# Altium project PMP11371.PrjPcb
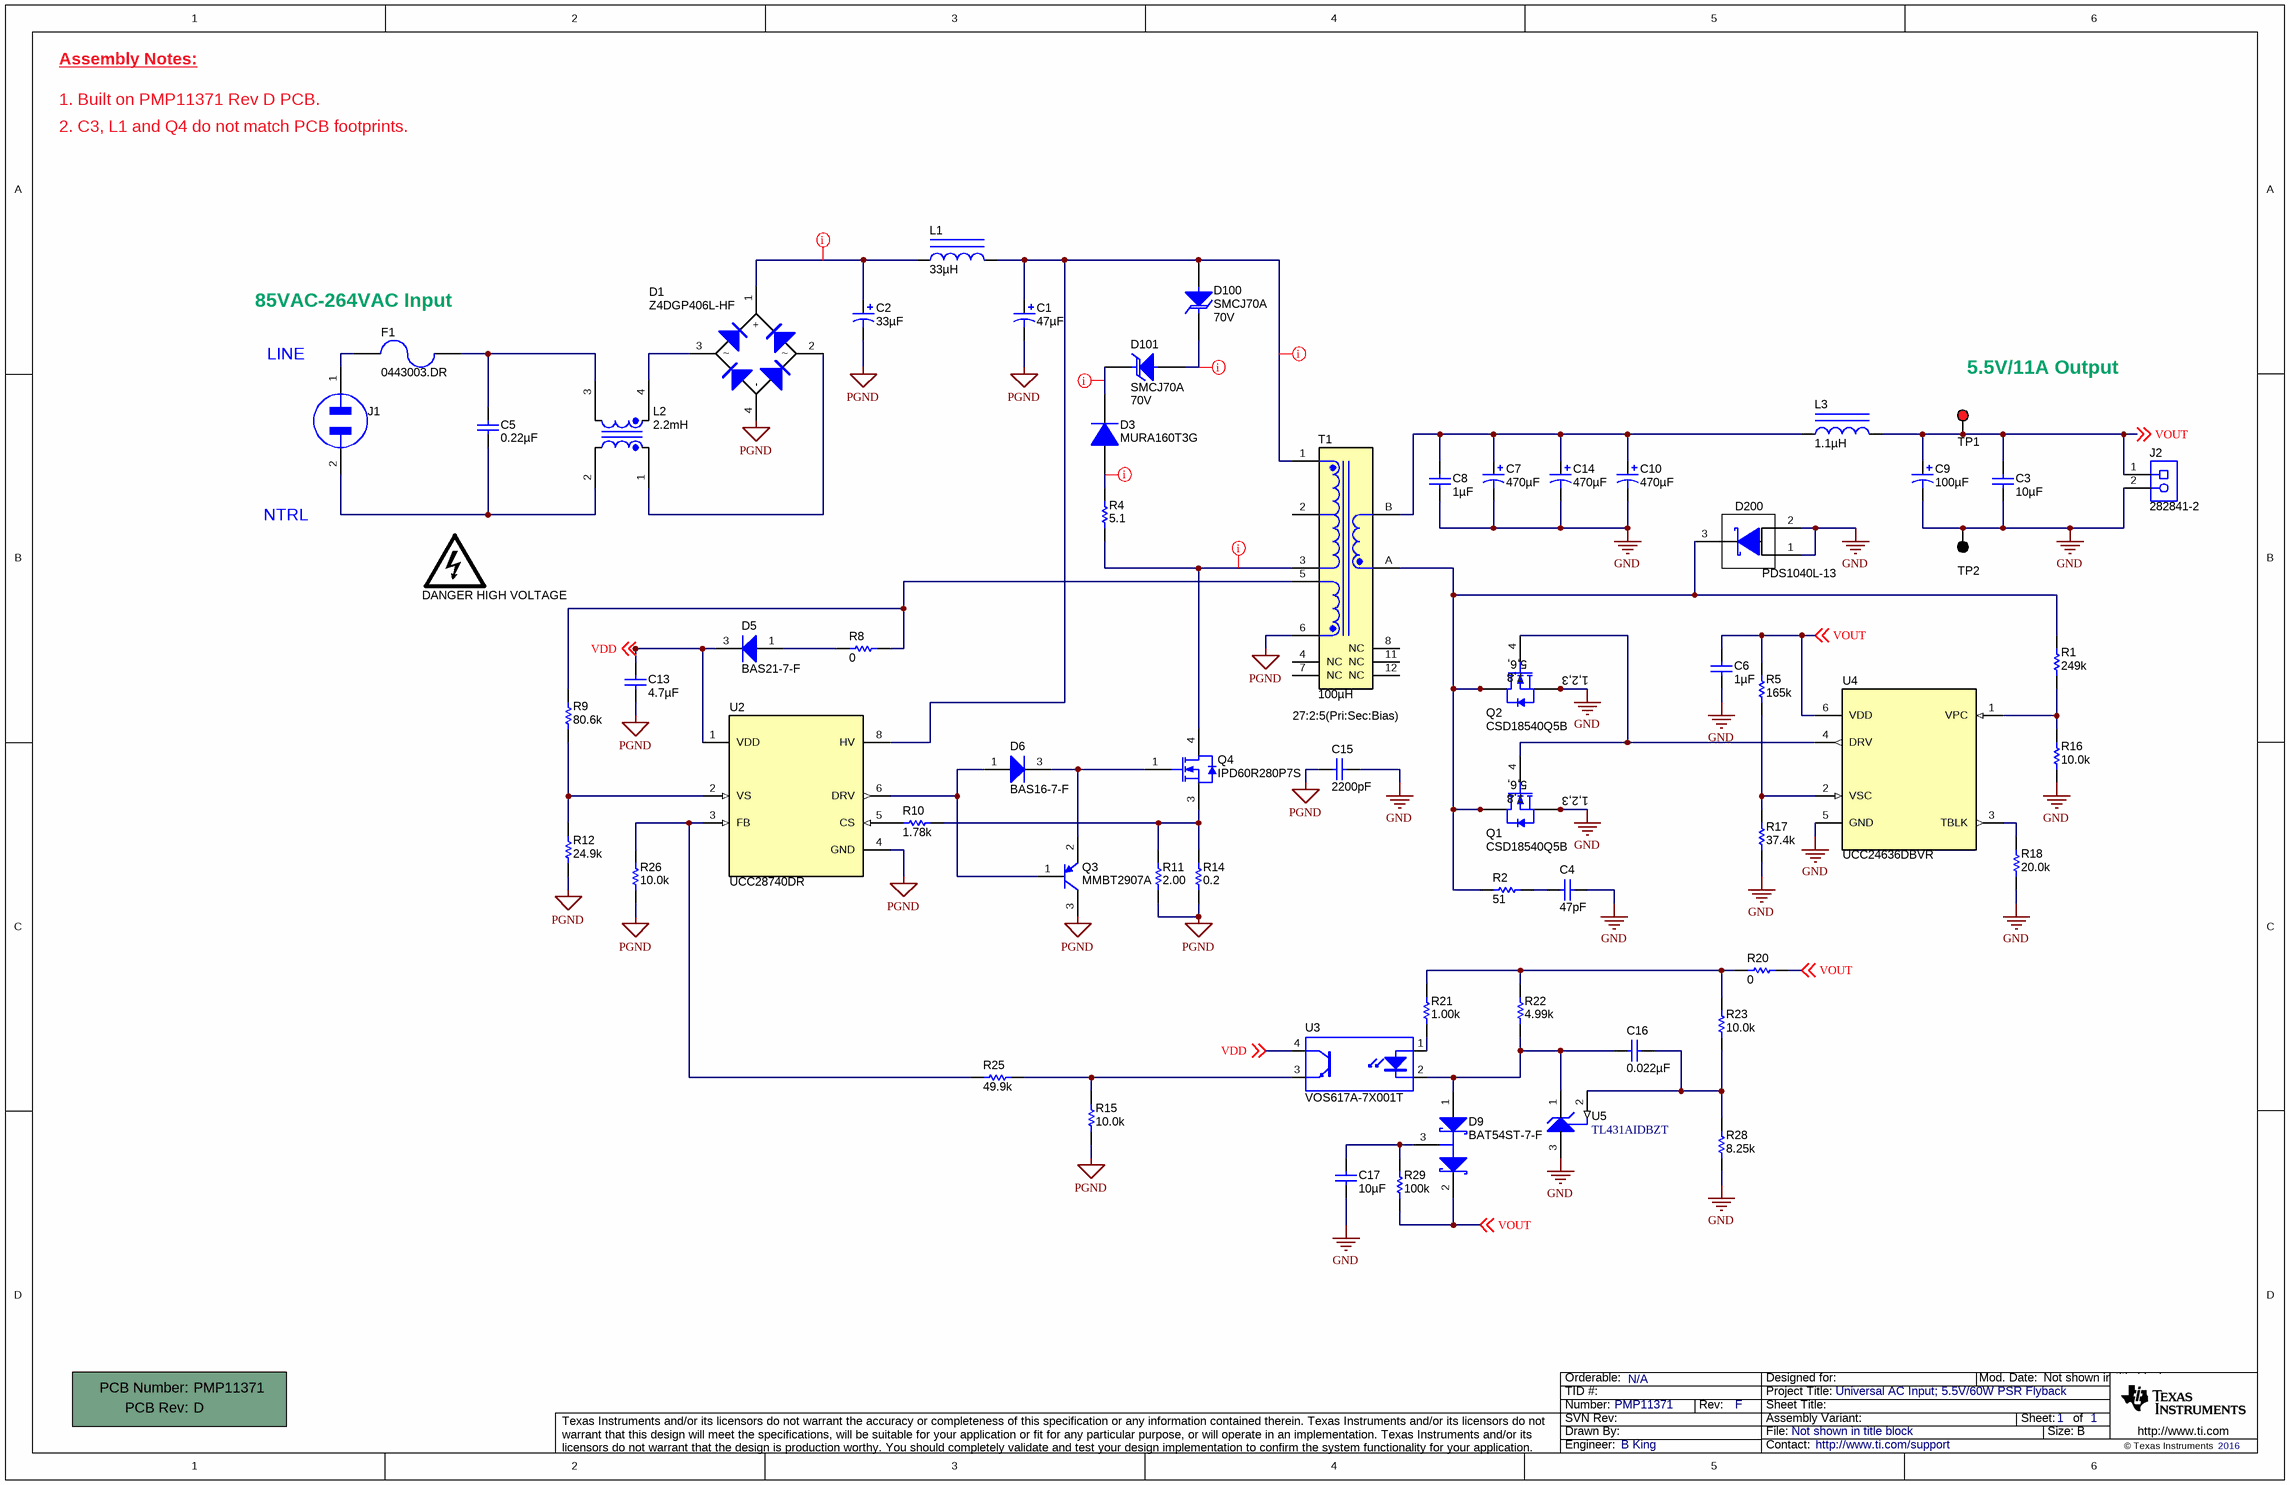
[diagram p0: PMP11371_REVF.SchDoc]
TechSupport: http://www.ti.com/support; SCH_Rev: F; PRJ_Title: Universal AC Input; 5.5V/60W PSR Flyback; PRJ_Number: PMP11371; PRJ_Engineer: B King; PCB_Rev: D; PCB_Layout: B King; EVM_Orderable: N/A; CopyrightYear: 2016
1 sheet, 64 parts. Net scope: global (net labels, ports and power ports of the same name join across sheets).
Board file: PMP11371_REVD.PcbDoc

## Sheet PMP11371_REVF.SchDoc
size 431 x 279 mm; Date: Not shown in title block; ApprovedBy: Not shown in title block; CheckedBy: Not shown in title block; Author: Not shown in title block; CompanyName: Not shown in title block; Engineer: Not shown in title block; Organization: Not shown in title block; Address1: Not shown in title block; Address2: Not shown in title block; Address3: Not shown in title block; Address4: Not shown in title block; DocumentNumber: 1; Revision: Use project parameter SCH_Rev; SheetNumber: 1; SheetTotal: 1; PageSetup: Record=PageOptions¦CenterHorizontal=True¦CenterVertical=True¦PrintScale=1.00¦XCorrection=1.00¦YCorrection=1.00¦PrintKind=0¦BorderSize=5000000¦LeftOffset=0¦BottomOffset=0¦Orientation=2¦PaperLength=1000¦PaperWidth=1000¦Scale=100¦PaperSource=15¦PrintQuality=600¦MediaType=1¦DitherType=10¦PaperKind=Letter¦PrintScaleMode=1

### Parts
!PCB  Printed Circuit Board  (value not drawn)  (mechanical)
C1  ValueDisplayed: 47µF  [CAPPR7.5-16X25]  (hidden comment: EEUED2G470)
C2  ValueDisplayed: 33µF  [CAPPR7.5-16X20]  (hidden comment: EEUED2G330S)
C3  ValueDisplayed: 10µF  [0805L]  (hidden comment: GRM21BR61C106KE15L)
C4  ValueDisplayed: 47pF  [0402L]  (hidden comment: GRM1555C1H470FA01D)
C5  ValueDisplayed: 0.22µF  [WCAP-FTX2_1800x600x1150]  (hidden comment: 890324025027CS)
C6  ValueDisplayed: 1µF  [0402L]  (hidden comment: GRM155R61A105KE15D)
C7  ValueDisplayed: 470µF  [CAPPRD350W60D800H800]  (hidden comment: 16SEPC470M)
C8  ValueDisplayed: 1µF  [0402L]  (hidden comment: GRM155R61A105KE15D)
C9  ValueDisplayed: 100µF  [CAPPR250W50D630H1120]  (hidden comment: EEU-EB1E101S)
C10  ValueDisplayed: 470µF  [CAPPRD350W60D800H800]  (hidden comment: 16SEPC470M)
C13  ValueDisplayed: 4.7µF  [1206_180L]  (hidden comment: GRM31CR71H475KA12L)
C14  ValueDisplayed: 470µF  [CAPPRD350W60D800H800]  (hidden comment: 16SEPC470M)
C15  ValueDisplayed: 2200pF  [CAPRD750W60D1050H1450]  (hidden comment: CS11-E2GA222MYNS)
C16  ValueDisplayed: 0.022µF  [0402L]  (hidden comment: GRM155R71H223KA12D)
C17  ValueDisplayed: 10µF  [0805L]  (hidden comment: GRM219R61A106KE44D)
D1  Z4DGP406L-HF  [Z4-D]
D3  MURA160T3G  [SMA]
D5  BAS21-7-F  [SOT-23]
D6  BAS16-7-F  [SOT-23]
D9  BAT54ST-7-F  [SOT-523]
D100  SMCJ70A  value 70V  [SMC_265]
D101  SMCJ70A  value 70V  [SMC_265]
D200  PDS1040L-13  [PowerDI5]
F1  0443003.DR  [FUSE_0443]
J1  770W-X2/10  [CONN_AC_770W-SERIES]  (value not drawn)
J2  282841-2  [TEC_282841-2]
L1  ValueDisplayed: 33µH  [DR73]  (hidden comment: DR73-330-R)
L2  ValueDisplayed: 2.2mH  [IND_WE-CMB-S]  (hidden comment: 744822222)
L3  ValueDisplayed: 1.1µH  [WE-HCI_7050]  (hidden comment: 744314110)
LOGO1  DANGER HIGH VOLTAGE  [IEC_HighVoltage_Small]  (no BOM)
Q1  CSD18540Q5B  [TRANS_NexFET_Q5B]
Q2  CSD18540Q5B  [TRANS_NexFET_Q5B]
Q3  MMBT2907A  [SOT-23]
Q4  IPD60R280P7S  [DDPAK]
R1  ValueDisplayed: 249k  [0402L]  (hidden comment: CRCW0402249KFKED)
R2  ValueDisplayed: 51  [1206L]  (hidden comment: CRCW120651R0JNEA)
R4  ValueDisplayed: 5.1  [2010L]  (hidden comment: CRCW20105R10JNEF)
R5  ValueDisplayed: 165k  [0402L]  (hidden comment: CRCW0402165KFKED)
R8  ValueDisplayed: 0  [0402L]  (hidden comment: CRCW04020000Z0ED)
R9  ValueDisplayed: 80.6k  [0402L]  (hidden comment: CRCW040280K6FKED)
R10  ValueDisplayed: 1.78k  [0402L]  (hidden comment: CRCW04021K78FKED)
R11  ValueDisplayed: 2.00  [0603L]  (hidden comment: CRCW06032R00FKEA)
R12  ValueDisplayed: 24.9k  [0402L]  (hidden comment: CRCW040224K9FKED)
R14  ValueDisplayed: 0.2  [2010L]  (hidden comment: CSRN2010FKR200)
R15  ValueDisplayed: 10.0k  [0402L]  (hidden comment: CRCW040210K0FKED)
R16  ValueDisplayed: 10.0k  [0402L]  (hidden comment: CRCW040210K0FKED)
R17  ValueDisplayed: 37.4k  [0402L]  (hidden comment: CRCW040237K4FKED)
R18  ValueDisplayed: 20.0k  [0402L]  (hidden comment: CRCW040220K0FKED)
R20  ValueDisplayed: 0  [0402L]  (hidden comment: CRCW04020000Z0ED)
R21  ValueDisplayed: 1.00k  [0402L]  (hidden comment: CRCW04021K00FKED)
R22  ValueDisplayed: 4.99k  [0402L]  (hidden comment: CRCW04024K99FKED)
R23  ValueDisplayed: 10.0k  [0402L]  (hidden comment: CRCW040210K0FKED)
R25  ValueDisplayed: 49.9k  [0402L]  (hidden comment: CRCW040249K9FKED)
R26  ValueDisplayed: 10.0k  [0402L]  (hidden comment: CRCW040210K0FKED)
R28  ValueDisplayed: 8.25k  [0402L]  (hidden comment: CRCW04028K25FKED)
R29  ValueDisplayed: 100k  [0402L]  (hidden comment: CRCW0402100KFKED)
T1  ValueDisplayed: 100µH  [Renco_RLTI-1174]  (hidden comment: RLTI-1174)
TP1  5000  [Keystone5000]  (value not drawn)
TP2  5001  [Keystone5001]  (value not drawn)
U2  UCC28740DR  [D0007A_L]
U3  VOS617A-7X001T  [SSOP-4_VISHAY]
U4  UCC24636DBVR  [DBV0006A_N]
U5  TL431AIDBZT  [DBZ0003A_L]

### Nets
GND: C3.2 C4.1 C6.2 C7.2(-) C8.2 C9.2(-) C10.2(-) C14.2(-) C15.1 C17.2 D200.1(A) D200.2(A) J2.2 Q1.1(S) Q1.2(S) Q1.3(S) Q2.1(S) Q2.2(S) Q2.3(S) R16.1 R17.1 R18.1 R28.1 TP2.1 U4.5(GND) U5.3(ANODE)
PGND: C1.2(-) C2.2(-) C13.2 C15.2 D1.4(-) Q3.3(C) R11.1 R12.1 R14.1 R15.1 R26.1 T1.6 U2.4(GND)
VDD: C13.1 D5.3(K) U2.1(VDD) U3.4(C) ; off-sheet VDD
VOUT: C3.1 C6.1 C9.1(+) D9.2(K) J2.1 L3.2 R5.2 R20.1 R29.1 TP1.1 U4.6(VDD) ; off-sheet VOUT
NetC1_1: C1.1(+) D100.2(A) L1.2 T1.1 U2.8(HV)
NetC2_1: C2.1(+) D1.1(+) L1.1
NetC4_2: C4.2 R2.1
NetC5_1: C5.1 F1.1 L2.3
NetC5_2: C5.2 J1.2(Hot) L2.2
NetC7_1: C7.1(+) C8.1 C10.1(+) C14.1(+) L3.1 T1.B(SR)
NetC16_1: C16.1 D9.1(A) R22.1 U3.2(K) U5.1(CATHODE)
NetC16_2: C16.2 R23.1 R28.2 U5.2(REF)
NetC17_1: C17.1 D9.3(C) R29.2
NetD1_2: D1.2 L2.1
NetD1_3: D1.3 L2.4
NetD3_1: D3.1(K) D101.1(K)
NetD3_2: D3.2(A) R4.2
NetD5_1: D5.1(A) R8.2
NetD6_1: D6.1(A) Q3.1(B) U2.6(DRV)
NetD6_3: D6.3(K) Q3.2(E) Q4.1(G)
NetD100_1: D100.1(K) D101.2(A)
NetD200_3: D200.3(K) Q1.5(D) Q1.6(D) Q1.7(D) Q1.8(D) Q2.5(D) Q2.6(D) Q2.7(D) Q2.8(D) R1.2 R2.2 T1.A(5.5V)
NetF1_2: F1.2 J1.1(Neutral)
NetQ1_4: Q1.4(G) Q2.4(G) U4.4(DRV)
NetQ4_3: Q4.3(S) R10.2 R11.2 R14.2
NetQ4_4: Q4.4(D) R4.1 T1.3
NetR1_1: R1.1 R16.2 U4.1(VPC)
NetR5_1: R5.1 R17.2 U4.2(VSC)
NetR8_1: R8.1 R9.2 T1.5
NetR9_1: R9.1 R12.2 U2.2(VS)
NetR10_1: R10.1 U2.5(CS)
NetR15_2: R15.2 R25.1 U3.3(E)
NetR18_2: R18.2 U4.3(TBLK)
NetR20_2: R20.2 R21.1 R22.2 R23.2
NetR21_2: R21.2 U3.1(A)
NetR25_2: R25.2 R26.2 U2.3(FB)

Not connected (* = marked no-connect by the designer): T1 2 4(NC) 7(NC) 8(NC) 11(NC) 12(NC)

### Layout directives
rule Clearance Constraint [Clearance = 15mil]: NetC1_1, NetD3_1, NetD3_2, NetD100_1, NetQ4_4
rule Clearance Constraint [Clearance = 20mil]: NetC2_1

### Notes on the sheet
- Assembly Notes:
- 1. Built on PMP11371 Rev D PCB.
- 2. C3, L1 and Q4 do not match PCB footprints.
- (near F1) 85VAC-264VAC Input
- (near J1) LINE
- (near TP1) 5.5V/11A Output
- NTRL
- 27:2:5(Pri:Sec:Bias)

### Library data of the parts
!PCB = PCB: Manufacturer: Any; PartNumber: PMP11371; SymbolCreator: a0412235
C1 = EEUED2G470: CAP, AL, 47 µF, 400 V, +/- 20%, 0.609529 ohm, TH; Manufacturer: Panasonic; Polarized: Y; CompType: Capacitor; Value: 47uF; U/M: EA; Cap_F: 0.000047; Tolerance_%: 20; VDC_V: 400; Value2: 400V; IRMS_A: 0.84; TaMin_C: -25; TaMax_C: 105; AC_Derating: 0.3; AEC Category: Q200
C2 = EEUED2G330S: CAP, AL, 33 µF, 400 V, +/- 20%, 0.868117 ohm, TH; Manufacturer: Panasonic; Polarized: Y; CompType: Capacitor; Value: 33uF; U/M: EA; Cap_F: 0.000033; Tolerance_%: 20; VDC_V: 400; Value2: 400V; IRMS_A: 0.73; TaMin_C: -25; TaMax_C: 105; AC_Derating: 0.3; AEC Category: Q200
C3 = GRM21BR61C106KE15L: CAP, CERM, 10 µF, 16 V, +/- 10%, X5R, 0805; Manufacturer: MuRata; Polarized: N; CompType: Capacitor; Value: 10uF; U/M: EA; Cap_F: 0.00001; Tolerance_%: 10; ESR_ohm: 0.008; Value1: 0.008 ohm; VDC_V: 16; Value2: 16V; TaMin_C: -55; TaMax_C: 85; Cap_Case: 0805; SizeArea_mm2: 2.5; SizeAreaWB_mm2: 6.75; SizeX_mm: 2; SizeY_mm: 1.25; SizeZ_mm: 1.45; AEC Category: Q200
C4 = GRM1555C1H470FA01D: CAP, CERM, 47 pF, 50 V, +/- 1%, C0G/NP0, 0402; Manufacturer: MuRata; Polarized: N; CompType: Capacitor; Value: 47pF; U/M: EA; Cap_F: 0.000000000047; Tolerance_%: 1; Value1: Unknown; VDC_V: 50; Value2: 50V; TaMin_C: -55; TaMax_C: 125; Cap_Case: 0402
C5 = 890324025027CS: CAP, Film, 0.22 µF, 275 V, +/- 10%, TH; Manufacturer: Wurth Elektronik; Polarized: N; CompType: Capacitor; Value: 0.22uF; U/M: EA; Cap_F: 0.00000022; Tolerance_%: 10; Value1: Unknown; VDC_V: 275; Value2: 275V; TaMin_C: -40; TaMax_C: 105; Cap_Case: 18x11.5x6mm; AEC Category: Q200
C6 C8 = GRM155R61A105KE15D: CAP, CERM, 1uF, 10V, +/-10%, X5R, 0402; Manufacturer: MuRata; Polarized: N; CompType: Capacitor; U/M: EA; Cap_F: 0.000001; Tolerance_%: 10; Value1: Unknown; TaMin_C: -55; TaMax_C: 85; Cap_Case: 0402
C7 C10 C14 = RL80J821MDN1KX: CAP POLYMER 470UF 20% 16V T/H; Manufacturer: Panasonic; Polarized: Y; CompType: Capacitor; U/M: EA; Cap_F: 0.00082; Tolerance_%: 20; Value1: 0.008 ohm; VDC_V: 6.3; ESR_ohm: 0.008; IRMS_A: 5.7; TaMin_C: -55; TaMax_C: 105; Cap_Case: Radial 3.5-8 x 8
C9 = EEU-EB1E101S: CAP, AL, 100 µF, 25 V, +/- 20%, TH; Manufacturer: Panasonic; Polarized: Y; CompType: Capacitor; Value: 100uF; U/M: EA; Cap_F: 0.0001; Tolerance_%: 20; Value1: Unknown; VDC_V: 25; Value2: 25V; IRMS_A: 0.095; TaMin_C: -40; TaMax_C: 105; Cap_Case: Radial 6.3x11.2; AEC Category: Q200; AEC Qualified: N
C13 = GRM31CR71H475KA12L: CAP, CERM, 4.7 µF, 50 V, +/- 10%, X7R, 1206; Manufacturer: MuRata; Polarized: N; CompType: Capacitor; Value: 4.7uF; U/M: EA; Cap_F: 0.0000047; Tolerance_%: 10; Value1: Unknown; VDC_V: 50; Value2: 50V; TaMin_C: -55; TaMax_C: 125; Cap_Case: 2220; AEC Category: Q200
C15 = CS11-E2GA222MYNS: CAP, CERM, 2200 pF, 250 V, +/- 20%, E, Radial Disc D10.5x7mm; Manufacturer: TDK; Polarized: N; CompType: Capacitor; Value: 2200pF; U/M: EA; Cap_F: 0.0000000022; Tolerance_%: 20; Value1: Unknown; VDC_V: 250; Value2: 250V; TaMin_C: -25; TaMax_C: 105; Cap_Case: Disc, 10.5x7mm
C16 = GRM155R71H223KA12D: CAP, CERM, 0.022 µF, 50 V, +/- 10%, X7R, 0402; Manufacturer: MuRata; Polarized: N; CompType: Capacitor; Value: 0.022uF; U/M: EA; Cap_F: 0.000000022; Tolerance_%: 10; Value1: Unknown; VDC_V: 50; Value2: 50V; TaMin_C: -55; TaMax_C: 125; Cap_Case: 0402
C17 = GRM219R61A106KE44D: CAP, CERM, 10 µF, 10 V, +/- 10%, X5R, 0805; Manufacturer: MuRata; Polarized: N; CompType: Capacitor; Value: 10uF; U/M: EA; Cap_F: 0.00001; Tolerance_%: 10; ESR_ohm: 0.005; Value1: 0.005 ohm; Value2: 10V; TaMin_C: -55; TaMax_C: 85; Cap_Case: 0805
D1 = Z4DGP406L-HF: Diode, P-N-Bridge, 600 V, 4 A, Z4-D; Manufacturer: Comchip Technology; U/M: EA; Vf_V: 0.95; Value: 600V; Value1: 4A; Value2: 0.95V; Io_A: 4; Vr_V: 600; TJmax_C: 175
D3 = MURA160T3G: Diode, Ultrafast, 600 V, 1 A, AEC-Q101, SMA; Manufacturer: ON Semiconductor; Value: 600V; U/M: EA; Vf_V: 1.05; Io_A: 1; Value1: 1A; Vr_V: 600; Value2: 1.05V; TJmax_C: 175; AEC Category: Q101; AEC Qualified: Y
D5 = BAS21-7-F: Diode, Switching, 200 V, 0.2 A, SOT-23; Manufacturer: Diodes Inc.; U/M: EA; Vf_V: 1.25; Io_A: 0.2; Value1: 0.2A; Vr_V: 200; Value2: 1.25V; TJmax_C: 150; RJC_CperW: 500; Value: 200V
D6 = BAS16-7-F: Diode, Ultrafast, 75 V, 0.3 A, SOT-23; Manufacturer: Diodes Inc.; U/M: EA; Vf_V: 1.125; Value: 75V; Value1: 0.3A; Value2: 1.125V; Io_A: 0.3; Vr_V: 75; AEC Category: Q101
D9 = BAT54ST-7-F: Diode, Schottky, 30 V, 0.2 A, SOT-523; Manufacturer: Diodes Inc.; U/M: EA; Vf_V: 1; Value: 30V; Value1: 0.2A; Value2: 1V; Io_A: 0.2; Vr_V: 30; TJmax_C: 125
D100 D101 = SMCJ70A: Diode, TVS, Uni, 70 V, 1500 W, SMC; Manufacturer: Littelfuse; U/M: EA; Power_W: 1500; Vr_V: 70; Value1: 1500W; RJA_CperW: 75; AEC Category: Q101; AEC Qualified: N
D200 = PDS1040L-13: Diode, Schottky, 40 V, 10 A, PowerDI5; Manufacturer: Diodes Inc.; U/M: EA; Vf_V: 0.49; Value: 40V; Value1: 10A; Value2: 0.49V; Io_A: 10; Vr_V: 40; TJmax_C: 150; RJC_CperW: 85
F1 = 0443003.DR: Fuse, 3 A, 250 V, SMD; Manufacturer: Littelfuse; U/M: EA; OpeningTime_100%_min: 4; OpeningTime_200%_max: 120; VDC_V: 250; Interrupt_AC: 50; Irating_A: 3; Rtyp_Ohm: 0.028; MeltingTyp: 51.44; Vdrop: 0.113; Soldering_Wave_MaxTemp_C: 260; Soldering_Reflow_MaxTemp_C: 217; Soldering_Reflow_MaxTime_s: 90
J1 = 770W-X2/10: AC Receptacle, 2.5A, R/A, TH; Manufacturer: Qualtek Electronics Corporation; SymbolCreator: a0412235; U/M: EA
J2 = 282841-2: Terminal Block, 2x1, 5.08mm, TH; Manufacturer: TE Connectivity; SymbolCreator: a0412235
L1 = DR73-330-R: Inductor, Shielded Drum Core, Ferrite, 33 µH, 1.31 A, 0.166 ohm, SMD; Manufacturer: Coiltronics; Value: 33uH; Ind_H: 33.0E-6; Imax_A: 1.31; Irms: 1.31A @ 40C rise; Isat: 1.35A @ 30% inductance drop; DCR_ohm: 0.166; Value2: 1.31A; AEC Category: Q200
L2 = 744822301: COMMON MODE CHOKE 2A 2 LN T/H; Manufacturer: Wurth Elektronik; SymbolCreator: a0412235; Value: 2.2mH; Ind_H: 1.0E-3; DCR_ohm: 0.035; CompType: Coupled Inductor
L3 = 744314110: Inductor, Shielded Drum Core, Superflux, 1.1 µH, 13 A, 0.0032 ohm, SMD; Manufacturer: Wurth Elektronik; Value: 1.1uH; Ind_H: 1.1E-6; Imax_A: 13; Irms: 15A @ 50C rise; Isat: 13A @ 30% inductance drop; DCR_ohm: 0.0032; Value2: 13A; AEC Category: Q200
LOGO1 = IEC_HighVoltage: IEC 61010-1 High Voltage Warning; SymbolCreator: a0412235
Q1 Q2 = CSD18540Q5B: MOSFET, N-CH, 60 V, 28 A, SON 5x6mm; Manufacturer: Texas Instruments; Alternate Manufacturer: None; Value: 60V; U/M: EA; ChType: N; VdsMax_V: 60; Value1: 0.0033 ohm; Rdson45_ohm: 0.0033; Value2: 41 nC; QgTyp_nC: 41; Vgs_V: 20; IdsMax_A: 28
Q3 = MMBT2907A, Fairchild Semiconductor: Transistor, PNP, 60 V, 0.8 A, SOT-23; CompType: BJT; PNP: 1; NPN: 0; Vceo_V: 60; Vcesat1_V: 1.6; Value: 60 V; IcRated_A: 0.8; Value1: 0.8 A; HfeMax: 300; TaMin_C: -55; TaMax_C: 150; U/M: EA; AEC Category: Q101
Q4 = CMP-0001164-2: MOSFET N-CH 600V 12A TO252-3; Alternate Manufacturer: None; Manufacturer: Infineon Technologies; SizeZ_mm: 4.445; ChType: N; Value2: 17 nC; SizeX_mm: 15.245; SizeY_mm: 10.16; Vgs_V: 20V; SizeArea_mm2: 154.8892; AEC Category: Q101; IdsMax_A: 9A; SizeAreaWB_mm2: 209.6992; U/M: EA; QgTyp_nC: 17
R1 = CRCW0402249KFKED: RES, 249 k, 1%, 0.063 W, 0402; Manufacturer: Vishay-Dale; CompType: Resistor; Value: 249k; Res_ohm: 249000; Tolerance_%: 1; Power_W: 0.063; Value2: 0.063W; VDC_V: 50; TempCo: 100 ppm/C; EIA_Code: E96; U/M: EA; AEC Category: Q200
R2 = CRCW120651R0JNEA: RES, 51, 5%, 0.25 W, 1206; Manufacturer: Vishay-Dale; CompType: Resistor; Value: 51; Value_Code: 51R0; Tolerance_%: 5; Power_W: 0.25; Value2: 0.25W; VDC_V: 200; TempCo: 200 ppm/C; EIA_Code: E24; U/M: EA
R4 = CRCW20105R10JNEF: RES, 5.1, 5%, 0.75 W, AEC-Q200 Grade 0, 2010; Manufacturer: Vishay-Dale; CompType: Resistor; Value: 5.1; Value_Code: 5R10; Tolerance_%: 5; Power_W: 0.75; Value2: 0.75W; VDC_V: 400; TempCo: 200 ppm/C; EIA_Code: E24; U/M: EA; AEC Category: Q200; AEC Qualified: Y; AEC Grade: 0
R5 = CRCW0402165KFKED: RES, 165 k, 1%, 0.063 W, 0402; Manufacturer: Vishay-Dale; CompType: Resistor; Value: 165k; Res_ohm: 165000; Tolerance_%: 1; Power_W: 0.063; Value2: 0.063W; VDC_V: 50; TempCo: 100 ppm/C; EIA_Code: E96; U/M: EA; AEC Category: Q200
R8 R20 = CRCW04020000Z0ED: RES, 0, 5%, 0.063 W, 0402; Manufacturer: Vishay-Dale; CompType: Resistor; Value: 0; Value_Code: 0000; Tolerance_%: 5; Power_W: 0.063; Value2: 0.063W; VDC_V: 50; TempCo: 200 ppm/C; EIA_Code: E24; U/M: EA
R9 = CRCW040280K6FKED: RES, 80.6 k, 1%, 0.063 W, 0402; Manufacturer: Vishay-Dale; CompType: Resistor; Value: 80.6k; Res_ohm: 80600; Value_Code: 80k6; Tolerance_%: 1; Power_W: 0.063; Value2: 0.063W; VDC_V: 50; TempCo: 100 ppm/C; EIA_Code: E96; U/M: EA; AEC Category: Q200
R10 = CRCW04021K78FKED: RES, 1.78 k, 1%, 0.063 W, 0402; Manufacturer: Vishay-Dale; CompType: Resistor; Value: 1.78k; Res_ohm: 1780; Value_Code: 1k78; Tolerance_%: 1; Power_W: 0.063; Value2: 0.063W; VDC_V: 50; TempCo: 100 ppm/C; EIA_Code: E96; U/M: EA
R11 = CRCW06032R00FKEA: RES, 2.00, 1%, 0.1 W, 0603; Manufacturer: Vishay-Dale; CompType: Resistor; Value: 2.00; Res_ohm: 2; Value_Code: 2R00; Tolerance_%: 1; Power_W: 0.1; Value2: 0.1W; VDC_V: 75; TempCo: 100 ppm/C; EIA_Code: E96; U/M: EA; AEC Category: Q200
R12 = CRCW040224K9FKED: RES, 24.9 k, 1%, 0.063 W, 0402; Manufacturer: Vishay-Dale; CompType: Resistor; Value: 24.9k; Res_ohm: 24900; Value_Code: 24k9; Tolerance_%: 1; Power_W: 0.063; Value2: 0.063W; VDC_V: 50; TempCo: 100 ppm/C; EIA_Code: E96; U/M: EA; AEC Category: Q200
R14 = CSRN2010FKR200: RES, 0.2, 1%, 1 W, 2010; Manufacturer: Stackpole Electronics Inc; CompType: Resistor; Value: 0.2; Value_Code: R200; Tolerance_%: 1; Value2: 1W; TempCo: 250 ppm/C; EIA_Code: E96; U/M: EA; AEC Category: Q200
R15 R16 R23 R26 = CRCW040210K0FKED: RES, 10.0 k, 1%, 0.063 W, 0402; Manufacturer: Vishay-Dale; CompType: Resistor; Value: 10.0k; Res_ohm: 10000; Value_Code: 10k0; Tolerance_%: 1; Power_W: 0.063; Value2: 0.063W; VDC_V: 50; TempCo: 100 ppm/C; EIA_Code: E96; U/M: EA
R17 = CRCW040237K4FKED: RES, 37.4 k, 1%, 0.063 W, 0402; Manufacturer: Vishay-Dale; CompType: Resistor; Value: 37.4k; Res_ohm: 37400; Value_Code: 37k4; Tolerance_%: 1; Power_W: 0.063; Value2: 0.063W; VDC_V: 50; TempCo: 100 ppm/C; EIA_Code: E96; U/M: EA
R18 = CRCW040220K0FKED: RES, 20.0 k, 1%, 0.063 W, 0402; Manufacturer: Vishay-Dale; CompType: Resistor; Value: 20.0k; Res_ohm: 20000; Value_Code: 20k0; Tolerance_%: 1; Power_W: 0.063; Value2: 0.063W; VDC_V: 50; TempCo: 100 ppm/C; EIA_Code: E96; U/M: EA
R21 = CRCW04021K00FKED: RES, 1.00 k, 1%, 0.063 W, 0402; Manufacturer: Vishay-Dale; CompType: Resistor; Value: 1.00k; Res_ohm: 1000; Value_Code: 1k00; Tolerance_%: 1; Power_W: 0.063; Value2: 0.063W; VDC_V: 50; TempCo: 100 ppm/C; EIA_Code: E96; U/M: EA; AEC Category: Q200
R22 = CRCW04024K99FKED: RES, 4.99 k, 1%, 0.063 W, 0402; Manufacturer: Vishay-Dale; CompType: Resistor; Value: 4.99k; Res_ohm: 4990; Value_Code: 4k99; Tolerance_%: 1; Power_W: 0.063; Value2: 0.063W; VDC_V: 50; TempCo: 100 ppm/C; EIA_Code: E96; U/M: EA
R25 = CRCW040249K9FKED: RES, 49.9 k, 1%, 0.063 W, 0402; Manufacturer: Vishay-Dale; CompType: Resistor; Value: 49.9k; Res_ohm: 49900; Value_Code: 49k9; Tolerance_%: 1; Power_W: 0.063; Value2: 0.063W; VDC_V: 50; TempCo: 100 ppm/C; EIA_Code: E96; U/M: EA; AEC Category: Q200
R28 = CRCW04028K25FKED: RES, 8.25 k, 1%, 0.063 W, 0402; Manufacturer: Vishay-Dale; CompType: Resistor; Value: 8.25k; Res_ohm: 8250; Value_Code: 8k25; Tolerance_%: 1; Power_W: 0.063; Value2: 0.063W; VDC_V: 50; TempCo: 100 ppm/C; EIA_Code: E96; U/M: EA; AEC Category: Q200
R29 = CRCW0402100KFKED: RES, 100 k, 1%, 0.063 W, 0402; Manufacturer: Vishay-Dale; CompType: Resistor; Value: 100k; Res_ohm: 100000; Tolerance_%: 1; Power_W: 0.063; Value2: 0.063W; VDC_V: 50; TempCo: 100 ppm/C; EIA_Code: E96; U/M: EA
T1 = RLTI-1174: Flyback Transformer, 100uH, TH; Manufacturer: Renco Electronics; SymbolCreator: Altium; Lp: 100; DCR_ohm: 0.05; LeakageL: 3; Ns1toNp: 0.71; Rs1: 0.18; Rs2: 0.0007
TP1 = 5000: Test Point, Miniature, Red, TH; Manufacturer: Keystone; CompType: Test Point Loop; U/M: EA
TP2 = 5001: Test Point, Miniature, Black, TH; Manufacturer: Keystone; CompType: Test Point Loop; U/M: EA
U2 = UCC28740DR: Constant-Voltage, Constant-Current Flyback Controller Using Opto-Coupler Feedback, D0007A; Manufacturer: Texas Instruments; SymbolCreator: a0412235; CompType: IC; U/M: EA
U3 = VOS617A-7X001T: OptoCoupler, Phototransitor, 80-160%, SSOP-4; Manufacturer: Vishay-Semiconductor; U/M: EA
U4 = UCC24636DBVR: SYNCRONOUS RECTIFIER CONTROLLER WITH LOW POWER STANDBY, DBV0006A; Alternate PartNumber: UCC24636DBVT; Manufacturer: Texas Instruments; SymbolCreator: a0411947; CompType: IC; U/M: EA
U5 = TL431AIDBZT: Adjustable Precision Shunt Regulator, 34 ppm / degC, 100 mA, -40 to 85 degC, 3-pin SOT-23 (DBZ), Green (RoHS & no Sb/Br); Manufacturer: Texas Instruments; Alternate PartNumber: Equivalent; Initial Accuracy @ 25/deg C(%): 1; Iout/Iz(Max)(mA): 100; Min Iz for Regulation(uA): 600; Rating: Catalog; SubFamily: Shunt Voltage Reference; Temp Coeff(Max)(ppm/ degree C): 92; Temp Coeff(Typ)(ppm/ degree C): 34; VO Adj(Max)(V): 36; VO Adj(Min)(V): 2.495

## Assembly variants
001: all parts fitted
